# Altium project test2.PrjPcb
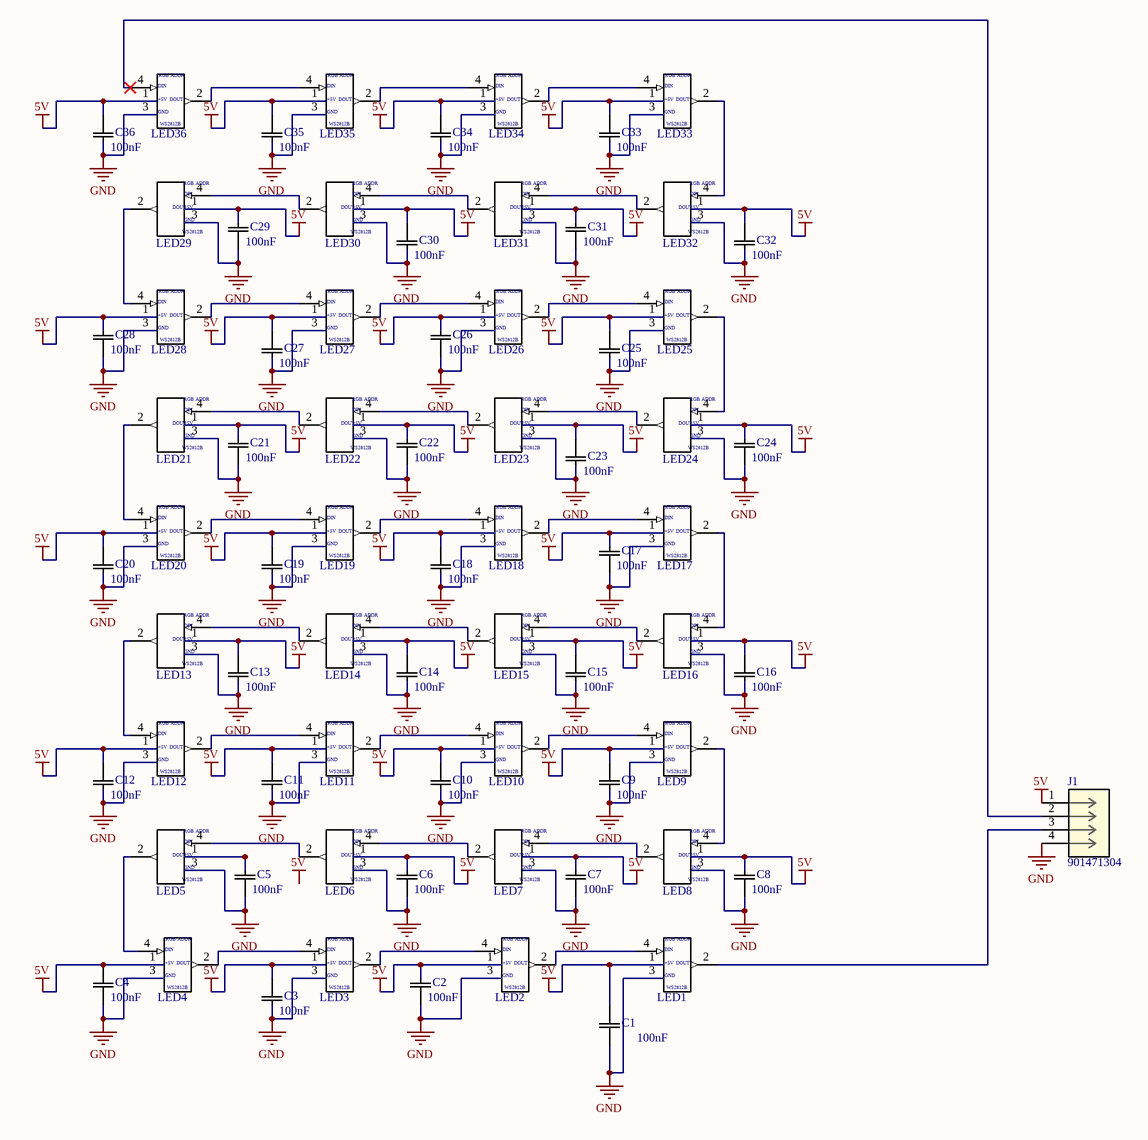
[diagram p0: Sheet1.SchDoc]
1 sheet, 73 parts. Net scope: global (net labels, ports and power ports of the same name join across sheets).
Board file: Ahds_rgb2.PcbDoc

## Sheet Sheet1.SchDoc
size B; SheetNumber: 1; SheetTotal: 1

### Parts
C1  100nF  [CAPC17595_87N_KEM]
C2  100nF  [CAPC17595_87N_KEM]
C3  100nF  [CAPC17595_87N_KEM]
C4  100nF  [CAPC17595_87N_KEM]
C5  100nF  [CAPC17595_87N_KEM]
C6  100nF  [CAPC17595_87N_KEM]
C7  100nF  [CAPC17595_87N_KEM]
C8  100nF  [CAPC17595_87N_KEM]
C9  100nF  [CAPC17595_87N_KEM]
C10  100nF  [CAPC17595_87N_KEM]
C11  100nF  [CAPC17595_87N_KEM]
C12  100nF  [CAPC17595_87N_KEM]
C13  100nF  [CAPC17595_87N_KEM]
C14  100nF  [CAPC17595_87N_KEM]
C15  100nF  [CAPC17595_87N_KEM]
C16  100nF  [CAPC17595_87N_KEM]
C17  100nF  [CAPC17595_87N_KEM]
C18  100nF  [CAPC17595_87N_KEM]
C19  100nF  [CAPC17595_87N_KEM]
C20  100nF  [CAPC17595_87N_KEM]
C21  100nF  [CAPC17595_87N_KEM]
C22  100nF  [CAPC17595_87N_KEM]
C23  100nF  [CAPC17595_87N_KEM]
C24  100nF  [CAPC17595_87N_KEM]
C25  100nF  [CAPC17595_87N_KEM]
C26  100nF  [CAPC17595_87N_KEM]
C27  100nF  [CAPC17595_87N_KEM]
C28  100nF  [CAPC17595_87N_KEM]
C29  100nF  [CAPC17595_87N_KEM]
C30  100nF  [CAPC17595_87N_KEM]
C31  100nF  [CAPC17595_87N_KEM]
C32  100nF  [CAPC17595_87N_KEM]
C33  100nF  [CAPC17595_87N_KEM]
C34  100nF  [CAPC17595_87N_KEM]
C35  100nF  [CAPC17595_87N_KEM]
C36  100nF  [CAPC17595_87N_KEM]
J1  901471304  [CONN04_901471304_MOL]
LED1  WS2812B  [*WS2812B_WS2812B(Primary)]  (value not drawn)
LED2  WS2812B  [*WS2812B_WS2812B(Primary)]  (value not drawn)
LED3  WS2812B  [*WS2812B_WS2812B(Primary)]  (value not drawn)
LED4  WS2812B  [*WS2812B_WS2812B(Primary)]  (value not drawn)
LED5  WS2812B  [*WS2812B_WS2812B(Primary)]  (value not drawn)
LED6  WS2812B  [*WS2812B_WS2812B(Primary)]  (value not drawn)
LED7  WS2812B  [*WS2812B_WS2812B(Primary)]  (value not drawn)
LED8  WS2812B  [*WS2812B_WS2812B(Primary)]  (value not drawn)
LED9  WS2812B  [*WS2812B_WS2812B(Primary)]  (value not drawn)
LED10  WS2812B  [*WS2812B_WS2812B(Primary)]  (value not drawn)
LED11  WS2812B  [*WS2812B_WS2812B(Primary)]  (value not drawn)
LED12  WS2812B  [*WS2812B_WS2812B(Primary)]  (value not drawn)
LED13  WS2812B  [*WS2812B_WS2812B(Primary)]  (value not drawn)
LED14  WS2812B  [*WS2812B_WS2812B(Primary)]  (value not drawn)
LED15  WS2812B  [*WS2812B_WS2812B(Primary)]  (value not drawn)
LED16  WS2812B  [*WS2812B_WS2812B(Primary)]  (value not drawn)
LED17  WS2812B  [*WS2812B_WS2812B(Primary)]  (value not drawn)
LED18  WS2812B  [*WS2812B_WS2812B(Primary)]  (value not drawn)
LED19  WS2812B  [*WS2812B_WS2812B(Primary)]  (value not drawn)
LED20  WS2812B  [*WS2812B_WS2812B(Primary)]  (value not drawn)
LED21  WS2812B  [*WS2812B_WS2812B(Primary)]  (value not drawn)
LED22  WS2812B  [*WS2812B_WS2812B(Primary)]  (value not drawn)
LED23  WS2812B  [*WS2812B_WS2812B(Primary)]  (value not drawn)
LED24  WS2812B  [*WS2812B_WS2812B(Primary)]  (value not drawn)
LED25  WS2812B  [*WS2812B_WS2812B(Primary)]  (value not drawn)
LED26  WS2812B  [*WS2812B_WS2812B(Primary)]  (value not drawn)
LED27  WS2812B  [*WS2812B_WS2812B(Primary)]  (value not drawn)
LED28  WS2812B  [*WS2812B_WS2812B(Primary)]  (value not drawn)
LED29  WS2812B  [*WS2812B_WS2812B(Primary)]  (value not drawn)
LED30  WS2812B  [*WS2812B_WS2812B(Primary)]  (value not drawn)
LED31  WS2812B  [*WS2812B_WS2812B(Primary)]  (value not drawn)
LED32  WS2812B  [*WS2812B_WS2812B(Primary)]  (value not drawn)
LED33  WS2812B  [*WS2812B_WS2812B(Primary)]  (value not drawn)
LED34  WS2812B  [*WS2812B_WS2812B(Primary)]  (value not drawn)
LED35  WS2812B  [*WS2812B_WS2812B(Primary)]  (value not drawn)
LED36  WS2812B  [*WS2812B_WS2812B(Primary)]  (value not drawn)

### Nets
5V: C1.1 C2.1 C3.1 C4.1 C6.1 C7.1 C8.1 C9.1 C10.1 C11.1 C12.1 C13.1 C14.1 C15.1 C16.1 C17.1 C18.1 C19.1 C20.1 C21.1 C22.1 C23.1 C24.1 C25.1 C26.1 C27.1 C28.1 C29.1 C30.1 C31.1 C32.1 C33.1 C34.1 C35.1 C36.1 J1.1 LED1.1 LED2.1 LED3.1 LED4.1 LED6.1 LED7.1 LED8.1 LED9.1 LED10.1 LED11.1 LED12.1 LED13.1 LED14.1 LED15.1 LED16.1 LED17.1 LED18.1 LED19.1 LED20.1 LED21.1 LED22.1 LED23.1 LED24.1 LED25.1 LED26.1 LED27.1 LED28.1 LED29.1 LED30.1 LED31.1 LED32.1 LED33.1 LED34.1 LED35.1 LED36.1
GND: C1.2 C2.2 C3.2 C4.2 C5.2 C6.2 C7.2 C8.2 C9.2 C10.2 C11.2 C12.2 C13.2 C14.2 C15.2 C16.2 C17.2 C18.2 C19.2 C20.2 C21.2 C22.2 C23.2 C24.2 C25.2 C26.2 C27.2 C28.2 C29.2 C30.2 C31.2 C32.2 C33.2 C34.2 C35.2 C36.2 J1.4 LED1.3 LED2.3 LED3.3 LED4.3 LED5.3 LED6.3 LED7.3 LED8.3 LED9.3 LED10.3 LED11.3 LED12.3 LED13.3 LED14.3 LED15.3 LED16.3 LED17.3 LED18.3 LED19.3 LED20.3 LED21.3 LED22.3 LED23.3 LED24.3 LED25.3 LED26.3 LED27.3 LED28.3 LED29.3 LED30.3 LED31.3 LED32.3 LED33.3 LED34.3 LED35.3 LED36.3
NetC5_1: C5.1 LED5.1
NetJ1_2: J1.2 LED36.4
NetJ1_3: J1.3 LED1.2(DO)
NetLED1_4: LED1.4 LED2.2(DO)
NetLED2_4: LED2.4 LED3.2(DO)
NetLED3_4: LED3.4 LED4.2(DO)
NetLED4_4: LED4.4 LED5.2(DO)
NetLED5_4: LED5.4 LED6.2(DO)
NetLED6_4: LED6.4 LED7.2(DO)
NetLED7_4: LED7.4 LED8.2(DO)
NetLED8_4: LED8.4 LED9.2(DO)
NetLED9_4: LED9.4 LED10.2(DO)
NetLED10_4: LED10.4 LED11.2(DO)
NetLED11_4: LED11.4 LED12.2(DO)
NetLED12_4: LED12.4 LED13.2(DO)
NetLED13_4: LED13.4 LED14.2(DO)
NetLED14_4: LED14.4 LED15.2(DO)
NetLED15_4: LED15.4 LED16.2(DO)
NetLED16_4: LED16.4 LED17.2(DO)
NetLED17_4: LED17.4 LED18.2(DO)
NetLED18_4: LED18.4 LED19.2(DO)
NetLED19_4: LED19.4 LED20.2(DO)
NetLED20_4: LED20.4 LED21.2(DO)
NetLED21_4: LED21.4 LED22.2(DO)
NetLED22_4: LED22.4 LED23.2(DO)
NetLED23_4: LED23.4 LED24.2(DO)
NetLED24_4: LED24.4 LED25.2(DO)
NetLED25_4: LED25.4 LED26.2(DO)
NetLED26_4: LED26.4 LED27.2(DO)
NetLED27_4: LED27.4 LED28.2(DO)
NetLED28_4: LED28.4 LED29.2(DO)
NetLED29_4: LED29.4 LED30.2(DO)
NetLED30_4: LED30.4 LED31.2(DO)
NetLED31_4: LED31.4 LED32.2(DO)
NetLED32_4: LED32.4 LED33.2(DO)
NetLED33_4: LED33.4 LED34.2(DO)
NetLED34_4: LED34.4 LED35.2(DO)
NetLED35_4: LED35.4 LED36.2(DO)

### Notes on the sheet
- Labels drawn without touching a wire or pin: 5V

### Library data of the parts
C1-C36 = C0603C103K4RECTU: ESD SMD Comm X7R, Ceramic, 0.01 uF, 10%, 16 VDC, X7R, SMD, MLCC, Temperature Stable, Electro Static Discharge, Class II, 0603; Manufacturer_Name: Kemet
J1 = 901471304: C-Grid III PCB Receptacle, 2.54mm Pitch, Single Row, Vertical, Shrouded, 4 Circuits, 0.76Âµm Gold (Au) Plating; Manufacturer_Name: Molex
LED1-LED36 = WS2812B: Intelligent control LED integrated light source; MF: Worldsemi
